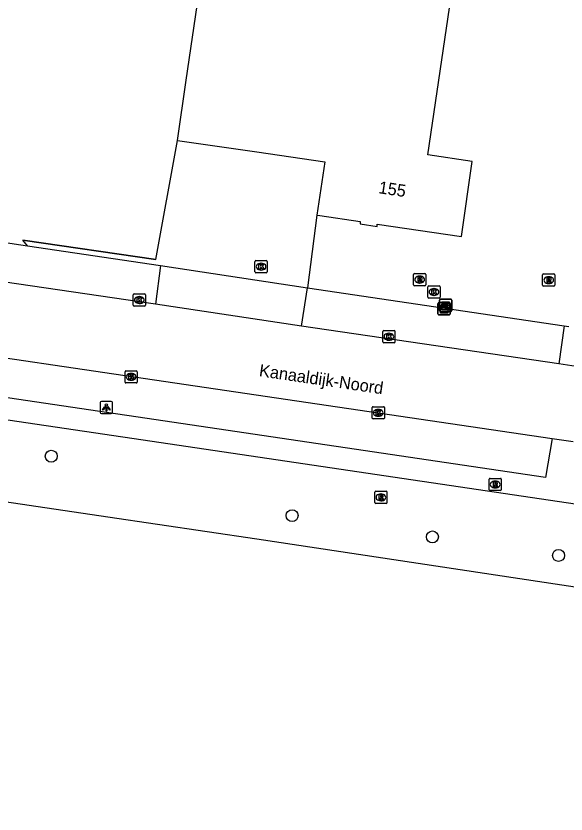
# Model space of a CAD drawing. Extents: x 163686 to 164493, y 382719 to 383870.
# Drawn here: x 163980.3 to 164025.4, y 382719.2 to 382784.6 of the extents above; entities that cross this region are included whole.
import ezdxf

# ---------------------------------------------------------------- set-up
doc = ezdxf.new("R2010")
doc.units = 0
for name, color, linetype in [('IMGEO_Boom', 7, 'Continuous'), ('IMGEO_Fietspad_open', 7, 'Continuous'), ('IMGEO_Groenvoorziening', 7, 'Continuous'), ('IMGEO_Hek', 7, 'Continuous'), ('IMGEO_Kast', 7, 'Continuous'), ('IMGEO_Kolk', 7, 'Continuous'), ('IMGEO_Lichtpunt', 7, 'Continuous'), ('IMGEO_Openbare_ruimte_label', 7, 'Continuous'), ('IMGEO_Pand', 7, 'Continuous'), ('IMGEO_Pand_nummerreeks', 7, 'Continuous'), ('IMGEO_Parkeervlak_open', 7, 'Continuous'), ('IMGEO_Rijbaan_lokaal_open', 7, 'Continuous'), ('IMGEO_Rioolput', 7, 'Continuous'), ('IMGEO_Terreindeel_open', 7, 'Continuous'), ('IMGEO_Waterloop', 7, 'Continuous')]:
    doc.layers.add(name, color=color, linetype=linetype)

msp = doc.modelspace()

# ---------------------------------------------------------------- linework, layer by layer
at = {"layer": 'IMGEO_Boom'}
for centre in [(163983.154, 382748.531), (164002.905, 382743.661), (164014.406, 382741.918), (164024.75, 382740.397)]:
    msp.add_circle(centre, 0.489, dxfattribs=at)
at = {"layer": 'IMGEO_Fietspad_open'}
for points in [[(164024.219, 382749.984), (164023.68, 382746.794), (163989.347, 382751.871), (163943.926, 382758.588), (163798.246, 382780.157), (163792.502, 382781.012)], [(164145.608, 382726.742), (164063.389, 382739.07), (163989.012, 382750.084), (163938.698, 382757.534)]]:
    msp.add_lwpolyline(points, dxfattribs=at)
at = {"layer": 'IMGEO_Groenvoorziening'}
msp.add_lwpolyline([(163981.208, 382765.781), (163980.82, 382766.248), (163991.738, 382764.656), (163993.496, 382774.395)], dxfattribs=at)
at = {"layer": 'IMGEO_Hek'}
for points in [[(163991.738, 382764.656), (163993.496, 382774.395)], [(163991.738, 382764.656), (163980.82, 382766.248)]]:
    msp.add_lwpolyline(points, dxfattribs=at)
at = {"layer": 'IMGEO_Kast'}
for p, q in [((164014.865, 382760.196), (164014.865, 382761.037)), ((164014.865, 382761.037), (164014.865, 382760.196)), ((164014.94, 382761.121), (164015.781, 382761.121)), ((164015.781, 382761.121), (164014.94, 382761.121)), ((164014.99, 382760.47), (164014.99, 382761.311)), ((164014.99, 382761.311), (164014.99, 382760.47)), ((164015.065, 382761.395), (164015.906, 382761.395)), ((164015.906, 382761.395), (164015.065, 382761.395)), ((164015.865, 382761.046), (164015.865, 382760.205)), ((164015.865, 382760.205), (164015.865, 382761.046)), ((164015.99, 382761.32), (164015.99, 382760.479)), ((164015.99, 382760.479), (164015.99, 382761.32)), ((164015.915, 382760.395), (164015.074, 382760.395)), ((164015.074, 382760.395), (164015.915, 382760.395)), ((164015.79, 382760.121), (164014.949, 382760.121)), ((164014.949, 382760.121), (164015.79, 382760.121))]:
    msp.add_line(p, q, dxfattribs=at)
for points in [[(164015.06, 382760.911), (164015.66, 382760.911), (164015.66, 382760.826), (164015.06, 382760.826), (164015.06, 382760.911)], [(164015.185, 382761.185), (164015.785, 382761.185), (164015.785, 382761.1), (164015.185, 382761.1), (164015.185, 382761.185)], [(164015.185, 382761.01), (164015.785, 382761.01), (164015.785, 382760.521), (164015.185, 382760.521), (164015.185, 382761.01)], [(164015.06, 382760.736), (164015.66, 382760.736), (164015.66, 382760.247), (164015.06, 382760.247), (164015.06, 382760.736)]]:
    msp.add_lwpolyline(points, dxfattribs=at)
for centre in [(164015.269, 382760.859), (164015.144, 382760.585)]:
    msp.add_circle(centre, 0.0377, dxfattribs=at)
for centre, start, end in [((164014.943, 382761.043), 92.4484, 184.28452), ((164014.943, 382761.043), 92.4484, 184.28452), ((164015.068, 382761.317), 92.4484, 184.28452), ((164015.068, 382761.317), 92.4484, 184.28452), ((164015.787, 382761.043), 2.4484, 94.28452), ((164015.787, 382761.043), 2.4484, 94.28452), ((164015.912, 382761.317), 2.4484, 94.28452), ((164015.912, 382761.317), 2.4484, 94.28452), ((164014.943, 382760.199), 182.4484, 274.28452), ((164014.943, 382760.199), 182.4484, 274.28452), ((164015.068, 382760.473), 182.4484, 274.28452), ((164015.068, 382760.473), 182.4484, 274.28452), ((164015.787, 382760.199), 272.4484, 4.28452), ((164015.787, 382760.199), 272.4484, 4.28452), ((164015.912, 382760.473), 272.4484, 4.28452), ((164015.912, 382760.473), 272.4484, 4.28452)]:
    msp.add_arc(centre, 0.0779, start, end, dxfattribs=at)
at = {"layer": 'IMGEO_Kolk'}
for p, q in [((163999.859, 382763.642), (163999.859, 382764.494)), ((163999.934, 382764.568), (164000.786, 382764.568)), ((164000.347, 382764.348), (164000.372, 382764.348)), ((164000.86, 382764.494), (164000.86, 382763.642)), ((164000.786, 382763.568), (163999.934, 382763.568)), ((164000.37, 382763.788), (164000.345, 382763.788)), ((164014.037, 382761.566), (164014.037, 382762.418)), ((164014.112, 382762.492), (164014.964, 382762.492)), ((164014.525, 382762.272), (164014.55, 382762.272)), ((164015.038, 382762.418), (164015.038, 382761.566)), ((163989.871, 382760.905), (163989.871, 382761.757)), ((163989.946, 382761.831), (163990.798, 382761.831)), ((163990.359, 382761.611), (163990.384, 382761.611)), ((163990.872, 382761.757), (163990.872, 382760.905)), ((164014.964, 382761.492), (164014.112, 382761.492)), ((164014.548, 382761.712), (164014.523, 382761.712)), ((163990.798, 382760.831), (163989.946, 382760.831)), ((163990.382, 382761.051), (163990.357, 382761.051)), ((164010.338, 382757.899), (164010.338, 382758.751)), ((164010.413, 382758.825), (164011.265, 382758.825)), ((164010.826, 382758.605), (164010.851, 382758.605)), ((164011.339, 382758.751), (164011.339, 382757.899)), ((164011.265, 382757.825), (164010.413, 382757.825)), ((164010.849, 382758.045), (164010.824, 382758.045)), ((163989.2, 382754.608), (163989.2, 382755.46)), ((163989.275, 382755.534), (163990.127, 382755.534)), ((163989.688, 382755.314), (163989.713, 382755.314)), ((163990.201, 382755.46), (163990.201, 382754.608)), ((163990.127, 382754.534), (163989.275, 382754.534)), ((163989.711, 382754.754), (163989.686, 382754.754)), ((164009.464, 382751.661), (164009.464, 382752.513)), ((164009.539, 382752.587), (164010.391, 382752.587)), ((164009.952, 382752.367), (164009.977, 382752.367)), ((164010.465, 382752.513), (164010.465, 382751.661)), ((164009.975, 382751.807), (164009.95, 382751.807)), ((164010.391, 382751.587), (164009.539, 382751.587))]:
    msp.add_line(p, q, dxfattribs=at)
for points in [[(163999.859, 382763.642), (163999.859, 382764.494)], [(163999.934, 382764.568), (164000.786, 382764.568)], [(164000.18, 382764.268), (164000.303, 382764.268), (164000.303, 382764.117), (164000.433, 382764.268), (164000.597, 382764.268), (164000.451, 382764.117), (164000.604, 382763.868), (164000.452, 382763.868), (164000.367, 382764.032), (164000.303, 382763.965), (164000.303, 382763.868), (164000.18, 382763.868), (164000.18, 382764.268)], [(164000.86, 382764.494), (164000.86, 382763.642)], [(164000.786, 382763.568), (163999.934, 382763.568)], [(164014.037, 382761.566), (164014.037, 382762.418)], [(164014.112, 382762.492), (164014.964, 382762.492)], [(164014.358, 382762.192), (164014.481, 382762.192), (164014.481, 382762.041), (164014.611, 382762.192), (164014.775, 382762.192), (164014.629, 382762.041), (164014.782, 382761.792), (164014.63, 382761.792), (164014.545, 382761.956), (164014.481, 382761.889), (164014.481, 382761.792), (164014.358, 382761.792), (164014.358, 382762.192)], [(164015.038, 382762.418), (164015.038, 382761.566)], [(163989.871, 382760.905), (163989.871, 382761.757)], [(163989.946, 382761.831), (163990.798, 382761.831)], [(163990.192, 382761.531), (163990.315, 382761.531), (163990.315, 382761.38), (163990.445, 382761.531), (163990.609, 382761.531), (163990.463, 382761.38), (163990.616, 382761.131), (163990.464, 382761.131), (163990.379, 382761.295), (163990.315, 382761.228), (163990.315, 382761.131), (163990.192, 382761.131), (163990.192, 382761.531)], [(163990.872, 382761.757), (163990.872, 382760.905)], [(164014.964, 382761.492), (164014.112, 382761.492)], [(163990.798, 382760.831), (163989.946, 382760.831)], [(164010.338, 382757.899), (164010.338, 382758.751)], [(164010.413, 382758.825), (164011.265, 382758.825)], [(164010.659, 382758.525), (164010.782, 382758.525), (164010.782, 382758.374), (164010.912, 382758.525), (164011.076, 382758.525), (164010.93, 382758.374), (164011.083, 382758.125), (164010.931, 382758.125), (164010.846, 382758.289), (164010.782, 382758.222), (164010.782, 382758.125), (164010.659, 382758.125), (164010.659, 382758.525)], [(164011.339, 382758.751), (164011.339, 382757.899)], [(164011.265, 382757.825), (164010.413, 382757.825)], [(163989.2, 382754.608), (163989.2, 382755.46)], [(163989.275, 382755.534), (163990.127, 382755.534)], [(163989.521, 382755.234), (163989.644, 382755.234), (163989.644, 382755.083), (163989.774, 382755.234), (163989.938, 382755.234), (163989.792, 382755.083), (163989.945, 382754.834), (163989.793, 382754.834), (163989.708, 382754.998), (163989.644, 382754.931), (163989.644, 382754.834), (163989.521, 382754.834), (163989.521, 382755.234)], [(163990.201, 382755.46), (163990.201, 382754.608)], [(163990.127, 382754.534), (163989.275, 382754.534)], [(164009.464, 382751.661), (164009.464, 382752.513)], [(164009.539, 382752.587), (164010.391, 382752.587)], [(164010.465, 382752.513), (164010.465, 382751.661)], [(164009.785, 382752.287), (164009.908, 382752.287), (164009.908, 382752.136), (164010.038, 382752.287), (164010.202, 382752.287), (164010.056, 382752.136), (164010.209, 382751.887), (164010.057, 382751.887), (164009.972, 382752.051), (164009.908, 382751.984), (164009.908, 382751.887), (164009.785, 382751.887), (164009.785, 382752.287)], [(164010.391, 382751.587), (164009.539, 382751.587)]]:
    msp.add_lwpolyline(points, dxfattribs=at)
for centre, start, end in [((163999.936, 382764.492), 91.55205, 178.44795), ((163999.936, 382764.492), 91.55205, 178.44795), ((164000.784, 382764.492), 1.55205, 88.44795), ((164000.784, 382764.492), 1.55205, 88.44795), ((163999.936, 382763.644), 181.55205, 268.44795), ((163999.936, 382763.644), 181.55205, 268.44795), ((164000.784, 382763.644), 271.55205, 358.44795), ((164000.784, 382763.644), 271.55205, 358.44795), ((164014.114, 382762.416), 91.55205, 178.44795), ((164014.114, 382762.416), 91.55205, 178.44795), ((164014.962, 382762.416), 1.55205, 88.44795), ((164014.962, 382762.416), 1.55205, 88.44795), ((163989.948, 382761.755), 91.55205, 178.44795), ((163989.948, 382761.755), 91.55205, 178.44795), ((163990.796, 382761.755), 1.55205, 88.44795), ((163990.796, 382761.755), 1.55205, 88.44795), ((164014.114, 382761.568), 181.55205, 268.44795), ((164014.114, 382761.568), 181.55205, 268.44795), ((164014.962, 382761.568), 271.55205, 358.44795), ((164014.962, 382761.568), 271.55205, 358.44795), ((163989.948, 382760.907), 181.55205, 268.44795), ((163989.948, 382760.907), 181.55205, 268.44795), ((163990.796, 382760.907), 271.55205, 358.44795), ((163990.796, 382760.907), 271.55205, 358.44795), ((164010.415, 382758.749), 91.55205, 178.44795), ((164010.415, 382758.749), 91.55205, 178.44795), ((164011.263, 382758.749), 1.55205, 88.44795), ((164011.263, 382758.749), 1.55205, 88.44795), ((164010.415, 382757.901), 181.55205, 268.44795), ((164010.415, 382757.901), 181.55205, 268.44795), ((164011.263, 382757.901), 271.55205, 358.44795), ((164011.263, 382757.901), 271.55205, 358.44795), ((163989.277, 382755.458), 91.55205, 178.44795), ((163989.277, 382755.458), 91.55205, 178.44795), ((163990.125, 382755.458), 1.55205, 88.44795), ((163990.125, 382755.458), 1.55205, 88.44795), ((163989.277, 382754.61), 181.55205, 268.44795), ((163989.277, 382754.61), 181.55205, 268.44795), ((163990.125, 382754.61), 271.55205, 358.44795), ((163990.125, 382754.61), 271.55205, 358.44795), ((164009.541, 382752.511), 91.55205, 178.44795), ((164009.541, 382752.511), 91.55205, 178.44795), ((164010.389, 382752.511), 1.55205, 88.44795), ((164010.389, 382752.511), 1.55205, 88.44795), ((164009.541, 382751.663), 181.55205, 268.44795), ((164009.541, 382751.663), 181.55205, 268.44795), ((164010.389, 382751.663), 271.55205, 358.44795), ((164010.389, 382751.663), 271.55205, 358.44795)]:
    msp.add_arc(centre, 0.0765, start, end, dxfattribs=at)
for centre, major_axis, ratio, start_param, end_param in [((164000.346, 382764.068), (-0.387, 0.002), 0.722429, 4.712389, 7.853982), ((164000.371, 382764.068), (-0.39, 0.002), 0.717154, 1.570796, 4.712389), ((164014.524, 382761.992), (-0.387, 0.002), 0.722429, 4.712389, 7.853982), ((164014.549, 382761.992), (-0.39, 0.002), 0.717154, 1.570796, 4.712389), ((163990.358, 382761.331), (-0.387, 0.002), 0.722429, 4.712389, 7.853982), ((163990.383, 382761.331), (-0.39, 0.002), 0.717154, 1.570796, 4.712389), ((164010.825, 382758.325), (-0.387, 0.002), 0.722429, 4.712389, 7.853982), ((164010.85, 382758.325), (-0.39, 0.002), 0.717154, 1.570796, 4.712389), ((163989.687, 382755.034), (-0.387, 0.002), 0.722429, 4.712389, 7.853982), ((163989.712, 382755.034), (-0.39, 0.002), 0.717154, 1.570796, 4.712389), ((164009.951, 382752.087), (-0.387, 0.002), 0.722429, 4.712389, 7.853982), ((164009.976, 382752.087), (-0.39, 0.002), 0.717154, 1.570796, 4.712389)]:
    msp.add_ellipse(centre, major_axis=major_axis, ratio=ratio, start_param=start_param, end_param=end_param, dxfattribs=at)
at = {"layer": 'IMGEO_Lichtpunt'}
for p, q in [((163988.078, 382753.027), (163987.27, 382753.027)), ((163988.078, 382753.027), (163987.27, 382753.027)), ((163987.176, 382752.932), (163987.176, 382752.125)), ((163987.176, 382752.932), (163987.176, 382752.125)), ((163988.172, 382752.125), (163988.172, 382752.932)), ((163988.172, 382752.125), (163988.172, 382752.932)), ((163987.27, 382752.031), (163988.078, 382752.031)), ((163987.27, 382752.031), (163988.078, 382752.031))]:
    msp.add_line(p, q, dxfattribs=at)
for points in [[(163987.55, 382752.596), (163987.589, 382752.568), (163987.401, 382752.306), (163987.363, 382752.333), (163987.55, 382752.596)], [(163987.652, 382752.548), (163987.699, 382752.548), (163987.699, 382752.226), (163987.652, 382752.226), (163987.652, 382752.548)], [(163987.762, 382752.568), (163987.8, 382752.595), (163987.987, 382752.333), (163987.948, 382752.305), (163987.762, 382752.568)]]:
    msp.add_lwpolyline(points, dxfattribs=at)
msp.add_circle((163987.675, 382752.73), 0.0994, dxfattribs=at)
for centre, start, end in [((163987.27, 382752.932), 90, 180), ((163987.27, 382752.932), 90, 180), ((163988.078, 382752.932), 0, 90), ((163988.078, 382752.932), 0, 90), ((163987.27, 382752.125), 180, 270), ((163987.27, 382752.125), 180, 270), ((163988.078, 382752.125), 270, 0), ((163988.078, 382752.125), 270, 360)]:
    msp.add_arc(centre, 0.0946, start, end, dxfattribs=at)
at = {"layer": 'IMGEO_Pand'}
for points in [[(163993.496, 382774.395), (163994.223, 382779.342), (163996.439, 382794.403)], [(164004.923, 382768.285), (164005.172, 382768.25), (164008.484, 382767.781), (164008.478, 382767.583), (164009.864, 382767.355), (164009.888, 382767.549), (164016.786, 382766.536), (164017.68, 382772.672), (164014.025, 382773.239), (164016.697, 382791.424)], [(163993.496, 382774.395), (164000, 382773.464), (164005.586, 382772.665), (164004.923, 382768.285)]]:
    msp.add_lwpolyline(points, dxfattribs=at)
at = {"layer": 'IMGEO_Parkeervlak_open'}
for points in [[(163975.188, 382766.675), (163981.208, 382765.781)], [(163981.208, 382765.781), (163992.106, 382764.162)], [(164004.157, 382762.319), (164025.213, 382759.215)]]:
    msp.add_lwpolyline(points, dxfattribs=at)
at = {"layer": 'IMGEO_Rijbaan_lokaal_open'}
for points in [[(163796.309, 382783.673), (163796.603, 382783.629), (163896.602, 382768.793), (163989.94, 382755.037), (164024.219, 382749.984)], [(163992.106, 382764.162), (163991.692, 382760.99)], [(163992.106, 382764.162), (164004.157, 382762.319)], [(163991.692, 382760.99), (163974.684, 382763.482)], [(164003.681, 382759.201), (164004.157, 382762.319)], [(164003.681, 382759.201), (163991.692, 382760.99)], [(164024.779, 382756.102), (164003.681, 382759.201)], [(164025.213, 382759.215), (164024.779, 382756.102)], [(164025.213, 382759.215), (164025.594, 382759.159)], [(164032.243, 382754.968), (164024.779, 382756.102)], [(164024.219, 382749.984), (164025.95, 382749.729)]]:
    msp.add_lwpolyline(points, dxfattribs=at)
at = {"layer": 'IMGEO_Rioolput'}
for p, q in [((164012.863, 382762.58), (164012.863, 382763.432)), ((164012.938, 382763.506), (164013.79, 382763.506)), ((164013.864, 382763.432), (164013.864, 382762.58)), ((164023.52, 382763.465), (164024.372, 382763.465)), ((164013.351, 382763.286), (164013.376, 382763.286)), ((164023.445, 382762.539), (164023.445, 382763.391)), ((164023.933, 382763.245), (164023.958, 382763.245)), ((164024.446, 382763.391), (164024.446, 382762.539)), ((164013.79, 382762.506), (164012.938, 382762.506)), ((164013.374, 382762.726), (164013.349, 382762.726)), ((164024.372, 382762.465), (164023.52, 382762.465)), ((164023.956, 382762.685), (164023.931, 382762.685)), ((164019.056, 382745.788), (164019.056, 382746.64)), ((164019.131, 382746.714), (164019.983, 382746.714)), ((164019.544, 382746.494), (164019.569, 382746.494)), ((164020.057, 382746.64), (164020.057, 382745.788)), ((164019.567, 382745.934), (164019.542, 382745.934)), ((164009.682, 382744.732), (164009.682, 382745.584)), ((164009.757, 382745.658), (164010.609, 382745.658)), ((164010.17, 382745.438), (164010.195, 382745.438)), ((164010.683, 382745.584), (164010.683, 382744.732)), ((164019.983, 382745.714), (164019.131, 382745.714)), ((164010.609, 382744.658), (164009.757, 382744.658)), ((164010.193, 382744.878), (164010.168, 382744.878))]:
    msp.add_line(p, q, dxfattribs=at)
for points in [[(164012.863, 382762.58), (164012.863, 382763.432)], [(164012.938, 382763.506), (164013.79, 382763.506)], [(164013.864, 382763.432), (164013.864, 382762.58)], [(164023.52, 382763.465), (164024.372, 382763.465)], [(164013.452, 382763.204), (164013.2, 382763.206), (164013.2, 382762.806)], [(164013.2, 382762.806), (164013.324, 382762.806), (164013.324, 382762.968), (164013.335, 382762.968)], [(164013.378, 382763.125), (164013.324, 382763.125), (164013.324, 382763.044)], [(164013.324, 382763.044), (164013.376, 382763.044)], [(164013.382, 382762.939), (164013.453, 382762.806), (164013.593, 382762.806), (164013.528, 382762.932)], [(164023.445, 382762.539), (164023.445, 382763.391)], [(164024.034, 382763.163), (164023.782, 382763.165), (164023.782, 382762.765)], [(164023.782, 382762.765), (164023.906, 382762.765), (164023.906, 382762.927), (164023.917, 382762.927)], [(164023.96, 382763.084), (164023.906, 382763.084), (164023.906, 382763.003)], [(164023.906, 382763.003), (164023.958, 382763.003)], [(164023.964, 382762.898), (164024.035, 382762.765), (164024.175, 382762.765), (164024.11, 382762.891)], [(164024.446, 382763.391), (164024.446, 382762.539)], [(164013.79, 382762.506), (164012.938, 382762.506)], [(164024.372, 382762.465), (164023.52, 382762.465)], [(164019.056, 382745.788), (164019.056, 382746.64)], [(164019.131, 382746.714), (164019.983, 382746.714)], [(164019.645, 382746.412), (164019.393, 382746.414), (164019.393, 382746.014)], [(164020.057, 382746.64), (164020.057, 382745.788)], [(164019.393, 382746.014), (164019.517, 382746.014), (164019.517, 382746.176), (164019.528, 382746.176)], [(164019.571, 382746.333), (164019.517, 382746.333), (164019.517, 382746.252)], [(164019.517, 382746.252), (164019.569, 382746.252)], [(164019.575, 382746.147), (164019.646, 382746.014), (164019.786, 382746.014), (164019.721, 382746.14)], [(164009.682, 382744.732), (164009.682, 382745.584)], [(164009.757, 382745.658), (164010.609, 382745.658)], [(164010.271, 382745.356), (164010.019, 382745.358), (164010.019, 382744.958)], [(164010.019, 382744.958), (164010.143, 382744.958), (164010.143, 382745.12), (164010.154, 382745.12)], [(164010.197, 382745.277), (164010.143, 382745.277), (164010.143, 382745.196)], [(164010.143, 382745.196), (164010.195, 382745.196)], [(164010.683, 382745.584), (164010.683, 382744.732)], [(164019.983, 382745.714), (164019.131, 382745.714)], [(164010.609, 382744.658), (164009.757, 382744.658)], [(164010.201, 382745.091), (164010.272, 382744.958), (164010.412, 382744.958), (164010.347, 382745.084)]]:
    msp.add_lwpolyline(points, dxfattribs=at)
for centre, radius, start, end in [((164012.94, 382763.43), 0.0765, 91.55205, 178.44795), ((164012.94, 382763.43), 0.0765, 91.55205, 178.44795), ((164013.788, 382763.43), 0.0765, 1.55205, 88.44795), ((164013.788, 382763.43), 0.0765, 1.55205, 88.44795), ((164023.522, 382763.389), 0.0765, 91.55205, 178.44795), ((164023.522, 382763.389), 0.0765, 91.55205, 178.44795), ((164024.37, 382763.389), 0.0765, 1.55205, 88.44795), ((164024.37, 382763.389), 0.0765, 1.55205, 88.44795), ((164013.334, 382762.915), 0.0533, 26.02933, 88.69889), ((164013.36, 382763.233), 0.19, 274.7715, 282.96867), ((164013.384, 382763.029), 0.0964, 77.00612, 93.18647), ((164013.398, 382763.086), 0.0378, 276.66336, 79.67722), ((164013.451, 382763.094), 0.109, 350.36119, 89.41601), ((164013.449, 382763.094), 0.112, 277.58423, 350.98172), ((164013.433, 382762.879), 0.108, 29.51342, 73.79051), ((164023.916, 382762.874), 0.0533, 26.02933, 88.69889), ((164023.942, 382763.192), 0.19, 274.7715, 282.96867), ((164023.966, 382762.988), 0.0964, 77.00612, 93.18647), ((164023.98, 382763.045), 0.0378, 276.66336, 79.67722), ((164024.033, 382763.053), 0.109, 350.36119, 89.41601), ((164024.031, 382763.053), 0.112, 277.58423, 350.98172), ((164024.015, 382762.838), 0.108, 29.51342, 73.79051), ((164012.94, 382762.582), 0.0765, 181.55205, 268.44795), ((164012.94, 382762.582), 0.0765, 181.55205, 268.44795), ((164013.788, 382762.582), 0.0765, 271.55205, 358.44795), ((164013.788, 382762.582), 0.0765, 271.55205, 358.44795), ((164023.522, 382762.541), 0.0765, 181.55205, 268.44795), ((164023.522, 382762.541), 0.0765, 181.55205, 268.44795), ((164024.37, 382762.541), 0.0765, 271.55205, 358.44795), ((164024.37, 382762.541), 0.0765, 271.55205, 358.44795), ((164019.133, 382746.638), 0.0765, 91.55205, 178.44795), ((164019.133, 382746.638), 0.0765, 91.55205, 178.44795), ((164019.644, 382746.302), 0.109, 350.36119, 89.41601), ((164019.981, 382746.638), 0.0765, 1.55205, 88.44795), ((164019.981, 382746.638), 0.0765, 1.55205, 88.44795), ((164019.133, 382745.79), 0.0765, 181.55205, 268.44795), ((164019.133, 382745.79), 0.0765, 181.55205, 268.44795), ((164019.527, 382746.123), 0.0533, 26.02933, 88.69889), ((164019.553, 382746.441), 0.19, 274.7715, 282.96867), ((164019.577, 382746.237), 0.0964, 77.00612, 93.18647), ((164019.591, 382746.294), 0.0378, 276.66336, 79.67722), ((164019.642, 382746.302), 0.112, 277.58423, 350.98172), ((164019.626, 382746.087), 0.108, 29.51342, 73.79051), ((164019.981, 382745.79), 0.0765, 271.55205, 358.44795), ((164019.981, 382745.79), 0.0765, 271.55205, 358.44795), ((164009.759, 382745.582), 0.0765, 91.55205, 178.44795), ((164009.759, 382745.582), 0.0765, 91.55205, 178.44795), ((164010.153, 382745.067), 0.0533, 26.02933, 88.69889), ((164010.179, 382745.385), 0.19, 274.7715, 282.96867), ((164010.203, 382745.181), 0.0964, 77.00612, 93.18647), ((164010.217, 382745.238), 0.0378, 276.66336, 79.67722), ((164010.27, 382745.246), 0.109, 350.36119, 89.41601), ((164010.268, 382745.246), 0.112, 277.58423, 350.98172), ((164010.252, 382745.031), 0.108, 29.51342, 73.79051), ((164010.607, 382745.582), 0.0765, 1.55205, 88.44795), ((164010.607, 382745.582), 0.0765, 1.55205, 88.44795), ((164009.759, 382744.734), 0.0765, 181.55205, 268.44795), ((164009.759, 382744.734), 0.0765, 181.55205, 268.44795), ((164010.607, 382744.734), 0.0765, 271.55205, 358.44795), ((164010.607, 382744.734), 0.0765, 271.55205, 358.44795)]:
    msp.add_arc(centre, radius, start, end, dxfattribs=at)
for centre, major_axis, ratio, start_param, end_param in [((164013.35, 382763.006), (-0.387, 0.002), 0.722429, 4.712389, 7.853982), ((164013.375, 382763.006), (-0.39, 0.002), 0.717154, 1.570796, 4.712389), ((164023.932, 382762.965), (-0.387, 0.002), 0.722429, 4.712389, 7.853982), ((164023.957, 382762.965), (-0.39, 0.002), 0.717154, 1.570796, 4.712389), ((164019.543, 382746.214), (-0.387, 0.002), 0.722429, 4.712389, 7.853982), ((164019.568, 382746.214), (-0.39, 0.002), 0.717154, 1.570796, 4.712389), ((164010.169, 382745.158), (-0.387, 0.002), 0.722429, 4.712389, 7.853982), ((164010.194, 382745.158), (-0.39, 0.002), 0.717154, 1.570796, 4.712389)]:
    msp.add_ellipse(centre, major_axis=major_axis, ratio=ratio, start_param=start_param, end_param=end_param, dxfattribs=at)
at = {"layer": 'IMGEO_Terreindeel_open'}
msp.add_lwpolyline([(164004.923, 382768.285), (164004.157, 382762.319)], dxfattribs=at)
at = {"layer": 'IMGEO_Waterloop'}
msp.add_lwpolyline([(164149.515, 382719.205), (164000, 382741.738), (163987.789, 382743.543), (163944.09, 382750), (163937.736, 382750.939)], dxfattribs=at)

# ---------------------------------------------------------------- texts
at = {"layer": 'IMGEO_Openbare_ruimte_label'}
msp.add_text('Kanaaldijk-Noord', height=1, rotation=351.65913, dxfattribs=at).set_placement((164000.15, 382755.094))
msp.add_text('Kanaaldijk-Noord', height=1, rotation=351.65913, dxfattribs=at).set_placement((164000.15, 382755.094))
at = {"layer": 'IMGEO_Pand_nummerreeks'}
msp.add_text('155', height=1, rotation=351.61312, dxfattribs=at).set_placement((164009.949, 382770.09))

doc.saveas('drawing.dxf')
